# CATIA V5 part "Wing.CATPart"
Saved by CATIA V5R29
Part number: Wing
Source: Unknown
Bounding box of the stored display mesh (mm): x -80 to 80, y 0 to 360, z -122.789 to 1.5
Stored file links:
  C:\가치같이\SmartFactory_BoxErectorConveyor\Boxing(over)\Wing.CATPart
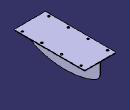
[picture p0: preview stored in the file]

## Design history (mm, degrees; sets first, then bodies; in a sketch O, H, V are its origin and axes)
Body1 (main body)
  Solid1 "PartBody": solid without history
